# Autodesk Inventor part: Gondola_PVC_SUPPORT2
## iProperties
Shininess: 64.0
Length Units: 11272
Angle Units: 11279
Time Units: 11290
Mass Units: 11286
Length Display Precision: 3
Angle Display Precision: 2
Compacted: True
Part Number: Gondola_PVC_SUPPORT2
Document SubType Name: Modeling
Created: 2004-08
Designer: John Blackburn
Manufacturer: Standard
Standards Organization: Custom
Material: PVC-Piping
Density: 0.0
Volumn: 0.0
Area: 0.0
PropertySet Name: Model Information
Control State: 0
Master: False
Checked Out: False
Author: John Blackburn
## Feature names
1. Base1
